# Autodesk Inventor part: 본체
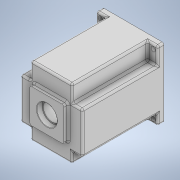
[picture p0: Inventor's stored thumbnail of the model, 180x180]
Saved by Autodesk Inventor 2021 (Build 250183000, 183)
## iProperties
Created: 2022-08
Part Number: 본체
Material: 일반
Document SubType Name: Modeling
Designer: Owner
Density: 1 g/cm^3
Appearance: 기본값
Author: Owner
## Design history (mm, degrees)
sketch "스케치1"
  geometry: L1 (55, 65)-(-55, 65); L2 (-55, 65)-(-55, -65); L3 (-55, -65)-(55, -65); L4 (55, -65)-(55, 65); L5 (55, 65)-(-55, -65); L6 (-55, 65)-(55, -65); 1 further point
  constraints: 12 end point, 2 midpoint, 2 parallel, 1 horizontal, 1 perpendicular
  dimensions: "d0" = 130 distance of L3.end L1.start; "d1" = 110 distance of L2.end L3.end
extrude "돌출1" new body sketch "스케치1" stored distance "d2" = 98; taper "d3" = 0 deg
sketch "스케치3"
  geometry: L1 (0, 0)-(0, 130) reference; L2 (0, 0)-(98, 0) reference; L3 (0, 120)-(16, 120); L4 (16, 120)-(16, 0); L5 (16, 0)-(0, 0); L6 (0, 0)-(0, 120); L7 (0, 130)-(98, 130) reference; L8 (49, 130)-(49, 0); L9 (82, 120)-(82, 0); L10 (98, 120)-(82, 120); L11 (98, 0)-(98, 130); L12 (98, 0)-(0, 0); 3 further points
  constraints: 18 end point, 5 symmetric about line, 4 point on line, 2 midpoint, 2 parallel, 1 horizontal, 1 perpendicular
  dimensions: "d9" = 16 distance of L3.start L3.end; "d10" = 10 distance between parallel lines of L7 L3
extrude "돌출3" cut sketch "스케치3" distance "d11" = 27; taper "d12" = 0 deg
sketch "스케치4"
  geometry: L1 (98, 10)-(98, 130) reference; L2 (98, 130)-(0, 130) reference; L3 (98, 10)-(82, 10); L4 (82, 10)-(82, 130); L5 (82, 130)-(98, 130); L6 (98, 130)-(98, 10); L7 (0, 0)-(98, 0) reference; L8 (49, 0)-(49, 130); L9 (16, 10)-(16, 130); L10 (0, 10)-(16, 10); L11 (0, 10)-(0, 130); L12 (0, 130)-(98, 130); 3 further points
  constraints: 18 end point, 5 symmetric about line, 2 midpoint, 2 parallel, 2 point on line, 1 horizontal, 1 perpendicular
  dimensions: "d13" = 16 distance of L1.start L3.end
extrude "돌출4" cut sketch "스케치4" distance "d14" = 17; taper "d15" = 0 deg
sketch "스케치5"
  geometry: L1 (6, -28)-(60, -28); L2 (60, -28)-(60, -82); L3 (60, -82)-(6, -82); L4 (6, -82)-(6, -28); L5 (6, -28)-(60, -82); L6 (60, -28)-(6, -82); 1 further point
  constraints: 12 end point, 2 midpoint, 2 parallel, 1 horizontal, 1 perpendicular
  dimensions: "d16" = 54 distance of L1.end L2.end; "d17" = 54 distance of L1.start L1.end
extrude "돌출5" join sketch "스케치5" distance "d18" = 7; taper "d19" = 0 deg
fillet "모깎기1" dims "d20" = 3
fillet "모깎기2" dims "d21" = 3
fillet "모깎기3" dims "d22" = 3
fillet "모깎기4" dims "d23" = 3
fillet "모깎기5" dims "d24" = 3
sketch "스케치6"
  geometry: L1 (0, -110)-(0, 0) reference; L2 (0, -55)-(98, -55); L3 (98, 0)-(98, -110) reference; L4 (98, 0)-(0, 0) reference; C1 r 3.5 at (7, -7); C2 r 3.5 at (91, -7); C3 r 3.5 at (7, -103); C4 r 3.5 at (91, -103); 1 further point
  constraints: 4 centre point, 2 end point, 2 midpoint, 2 symmetric about line, 2 other
  dimensions: "d25" = 7 distance from line of L4 C1.centre; "d26" = 7 distance from line of C1.centre L1; "d27" = 84 distance of C2.centre C1.centre; "d28" = 7 distance from line of L4 C2.centre; "d29" = 7 diameter of C1; "d30" = 7 diameter of C2
extrude "돌출6" cut sketch "스케치6" distance "d31" = 10; taper "d32" = 0 deg
fillet "모깎기6" dims "d33" = 3
fillet "모깎기7" dims "d34" = 3
sketch "스케치7"
  geometry: C1 r 14 at (33, -55); 1 further point
  constraints: 1 centre point, 1 coincident
  dimensions: "d35" = 28 diameter of C1
extrude "돌출7" cut sketch "스케치7" extent not by distance; stored distance "d36" = 10; taper "d37" = 0 deg
sketch "스케치8"
  geometry: C1 r 16 at (33, -55); 1 further point
  constraints: 1 centre point, 1 coincident
  dimensions: "d38" = 32 diameter of C1
extrude "돌출8" cut sketch "스케치8" distance "d39" = 8.3; taper "d40" = 0 deg
chamfer "모따기1" distance "d41" = 0.8; stored, may be unused: second distance "d42" = 2, angle "d43" = 30 deg
node "솔리드1"
